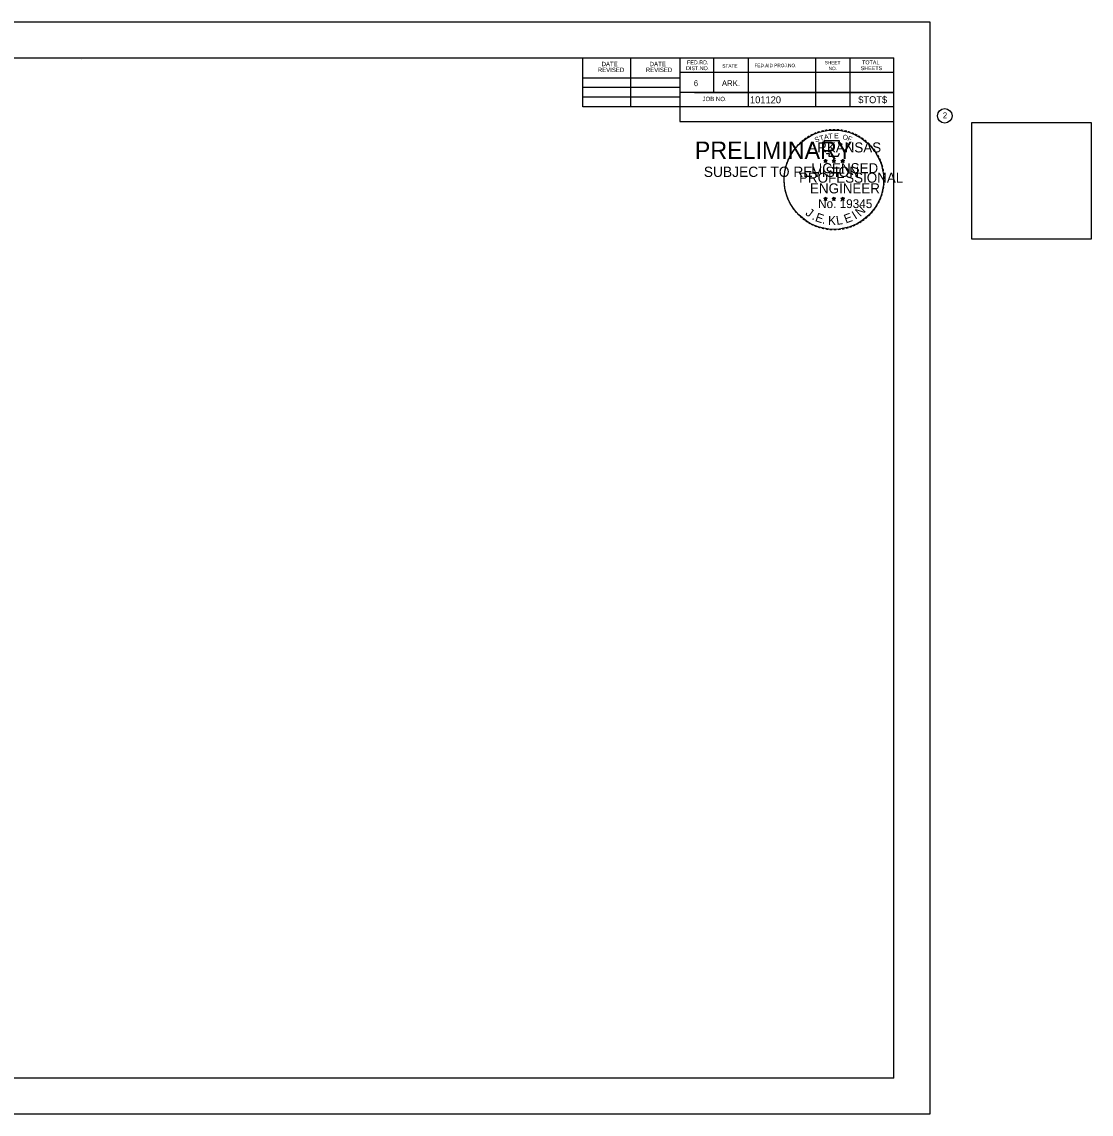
# Model space of a CAD drawing. Extents: x -7.3 to 35.8, y -0.5 to 21.5.
# Drawn here: x 14.21 to 35.75, y -0.5 to 21.5 of the extents above; entities that cross this region are included whole.
import ezdxf

# ---------------------------------------------------------------- set-up
doc = ezdxf.new("R2010")
doc.units = 0
for name, color, linetype in [('B_Border', 7, 'Continuous'), ('R_Border', 7, 'Continuous'), ('R_Border PE', 7, 'Continuous'), ('R_Border Prem', 7, 'Continuous'), ('R_No Plot', 7, 'Continuous')]:
    doc.layers.add(name, color=color, linetype=linetype)

msp = doc.modelspace()

# ---------------------------------------------------------------- linework, layer by layer
at = {"layer": 'B_Border'}
msp.add_lwpolyline([(-1.5, 21.5), (32.5, 21.5), (32.5, -0.5), (-1.5, -0.5)], close=True, dxfattribs=at)
at = {"layer": 'R_Border'}
for p, q in [((0.155, 20.773), (31.773, 20.773)), ((15.407, 20.747), (15.407, 20.747)), ((15.407, 20.747), (15.407, 20.747)), ((25.509, 19.785), (25.509, 20.773)), ((26.477, 19.785), (26.477, 20.773)), ((27.463, 20.773), (27.463, 19.493)), ((28.147, 20.773), (28.147, 20.079)), ((28.841, 20.773), (28.841, 19.785)), ((30.199, 20.773), (30.199, 19.785)), ((30.893, 20.773), (30.893, 19.785)), ((31.773, 0.227), (31.773, 20.773)), ((31.773, 20.479), (27.463, 20.479)), ((31.773, 20.481), (31.773, 20.481)), ((25.509, 20.371), (27.463, 20.371)), ((25.509, 20.185), (27.463, 20.185)), ((31.773, 20.079), (27.463, 20.079)), ((27.759, 20.079), (31.773, 20.079)), ((25.509, 19.991), (27.463, 19.991)), ((31.773, 19.785), (25.509, 19.785)), ((27.463, 19.493), (31.773, 19.493)), ((31.773, 0.227), (0.155, 0.227))]:
    msp.add_line(p, q, dxfattribs=at)
msp.add_circle((32.802, 19.607), 0.147, dxfattribs=at)
at = {"layer": 'R_Border PE'}
for p, q in [((30.365, 18.71), (30.4, 18.699)), ((30.365, 18.71), (30.391, 18.706)), ((30.365, 18.71), (30.389, 18.698)), ((30.4, 18.736), (30.396, 18.71)), ((30.4, 18.699), (30.4, 18.736)), ((30.4, 18.736), (30.405, 18.711)), ((30.434, 18.71), (30.4, 18.699)), ((30.434, 18.71), (30.406, 18.705)), ((30.434, 18.71), (30.415, 18.7)), ((30.534, 18.71), (30.569, 18.699)), ((30.534, 18.71), (30.559, 18.706)), ((30.534, 18.71), (30.557, 18.698)), ((30.569, 18.736), (30.565, 18.71)), ((30.569, 18.699), (30.569, 18.736)), ((30.569, 18.736), (30.573, 18.711)), ((30.603, 18.71), (30.569, 18.699)), ((30.603, 18.71), (30.574, 18.705)), ((30.603, 18.71), (30.583, 18.7)), ((30.711, 18.709), (30.746, 18.698)), ((30.711, 18.709), (30.736, 18.704)), ((30.711, 18.709), (30.735, 18.697)), ((30.746, 18.734), (30.742, 18.709)), ((30.746, 18.698), (30.746, 18.734)), ((30.746, 18.734), (30.75, 18.709)), ((30.782, 18.709), (30.746, 18.698)), ((30.782, 18.709), (30.752, 18.704)), ((30.782, 18.709), (30.76, 18.699)), ((30.378, 18.669), (30.4, 18.699)), ((30.378, 18.669), (30.391, 18.693)), ((30.378, 18.669), (30.399, 18.69)), ((30.422, 18.669), (30.399, 18.69)), ((30.422, 18.669), (30.4, 18.699)), ((30.422, 18.669), (30.407, 18.698)), ((30.546, 18.669), (30.569, 18.699)), ((30.546, 18.669), (30.56, 18.693)), ((30.546, 18.669), (30.568, 18.69)), ((30.59, 18.669), (30.568, 18.69)), ((30.59, 18.669), (30.569, 18.699)), ((30.59, 18.669), (30.575, 18.698)), ((30.724, 18.668), (30.746, 18.698)), ((30.724, 18.668), (30.737, 18.692)), ((30.724, 18.668), (30.746, 18.689)), ((30.767, 18.668), (30.746, 18.698)), ((30.767, 18.668), (30.746, 18.689)), ((30.767, 18.668), (30.754, 18.697)), ((30.364, 17.947), (30.399, 17.935)), ((30.364, 17.947), (30.391, 17.942)), ((30.364, 17.947), (30.389, 17.934)), ((30.378, 17.905), (30.399, 17.935)), ((30.378, 17.905), (30.391, 17.93)), ((30.378, 17.905), (30.399, 17.928)), ((30.399, 17.972), (30.395, 17.947)), ((30.399, 17.935), (30.399, 17.972)), ((30.399, 17.972), (30.404, 17.947)), ((30.434, 17.947), (30.399, 17.935)), ((30.422, 17.905), (30.399, 17.935)), ((30.422, 17.905), (30.399, 17.927)), ((30.434, 17.947), (30.405, 17.942)), ((30.422, 17.905), (30.407, 17.934)), ((30.434, 17.947), (30.415, 17.937)), ((30.533, 17.947), (30.568, 17.935)), ((30.533, 17.947), (30.559, 17.942)), ((30.533, 17.947), (30.557, 17.934)), ((30.546, 17.905), (30.568, 17.935)), ((30.546, 17.905), (30.559, 17.93)), ((30.546, 17.905), (30.568, 17.928)), ((30.568, 17.972), (30.564, 17.947)), ((30.568, 17.935), (30.568, 17.972)), ((30.568, 17.972), (30.572, 17.947)), ((30.603, 17.947), (30.568, 17.935)), ((30.589, 17.905), (30.568, 17.935)), ((30.589, 17.905), (30.568, 17.927)), ((30.603, 17.947), (30.573, 17.942)), ((30.589, 17.905), (30.575, 17.934)), ((30.603, 17.947), (30.581, 17.937)), ((30.711, 17.946), (30.746, 17.934)), ((30.711, 17.946), (30.736, 17.941)), ((30.711, 17.946), (30.735, 17.933)), ((30.724, 17.904), (30.746, 17.934)), ((30.724, 17.904), (30.737, 17.929)), ((30.724, 17.904), (30.746, 17.927)), ((30.746, 17.971), (30.742, 17.946)), ((30.746, 17.934), (30.746, 17.971)), ((30.746, 17.971), (30.75, 17.946)), ((30.782, 17.946), (30.746, 17.934)), ((30.767, 17.904), (30.746, 17.934)), ((30.767, 17.904), (30.746, 17.926)), ((30.782, 17.946), (30.752, 17.941)), ((30.767, 17.904), (30.753, 17.933)), ((30.782, 17.946), (30.76, 17.935))]:
    msp.add_line(p, q, dxfattribs=at)
for points in [[(30.369, 19.101), (30.396, 19.017)], [(30.722, 19.009), (30.737, 19.037), (30.669, 19.035), (30.682, 19.101), (30.369, 19.101)], [(30.4, 18.736), (30.422, 18.669), (30.365, 18.71), (30.434, 18.71), (30.378, 18.669), (30.4, 18.736)], [(30.419, 18.857), (30.419, 18.848), (30.475, 18.846), (30.469, 18.798), (30.658, 18.798), (30.679, 18.852)], [(30.569, 18.736), (30.59, 18.669), (30.534, 18.71), (30.603, 18.71), (30.546, 18.669), (30.569, 18.736)], [(30.746, 18.734), (30.767, 18.668), (30.711, 18.709), (30.782, 18.709), (30.724, 18.668), (30.746, 18.734)], [(30.399, 17.972), (30.422, 17.905), (30.364, 17.947), (30.434, 17.947), (30.378, 17.905), (30.399, 17.972)], [(30.568, 17.972), (30.589, 17.905), (30.533, 17.947), (30.603, 17.947), (30.546, 17.905), (30.568, 17.972)], [(30.746, 17.971), (30.767, 17.904), (30.711, 17.946), (30.782, 17.946), (30.724, 17.904), (30.746, 17.971)]]:
    msp.add_lwpolyline(points, dxfattribs=at)
for centre, radius in [((30.57, 18.321), 1), ((30.399, 18.698), 0.0174), ((30.399, 18.698), 0.0146), ((30.399, 18.698), 0.0117), ((30.399, 18.698), 0.00999), ((30.399, 18.698), 0.00753), ((30.399, 18.698), 0.00499), ((30.399, 18.698), 0.00299), ((30.567, 18.698), 0.0174), ((30.567, 18.698), 0.0146), ((30.567, 18.698), 0.0117), ((30.567, 18.698), 0.00999), ((30.567, 18.698), 0.00753), ((30.567, 18.698), 0.00499), ((30.567, 18.698), 0.00299), ((30.745, 18.697), 0.0174), ((30.745, 18.697), 0.0146), ((30.745, 18.697), 0.0117), ((30.745, 18.697), 0.00999), ((30.745, 18.697), 0.00753), ((30.745, 18.697), 0.00499), ((30.745, 18.697), 0.00299), ((30.399, 17.935), 0.0174), ((30.399, 17.935), 0.0146), ((30.399, 17.935), 0.0117), ((30.399, 17.935), 0.00999), ((30.399, 17.935), 0.00753), ((30.399, 17.935), 0.00499), ((30.399, 17.935), 0.00299), ((30.567, 17.935), 0.0174), ((30.567, 17.935), 0.0146), ((30.567, 17.935), 0.0117), ((30.567, 17.935), 0.00999), ((30.567, 17.935), 0.00753), ((30.567, 17.935), 0.00499), ((30.567, 17.935), 0.00299), ((30.745, 17.934), 0.0174), ((30.745, 17.934), 0.0146), ((30.745, 17.934), 0.0117), ((30.745, 17.934), 0.00999), ((30.745, 17.934), 0.00753), ((30.745, 17.934), 0.00499), ((30.745, 17.934), 0.00299)]:
    msp.add_circle(centre, radius, dxfattribs=at)
at = {"layer": 'R_No Plot'}
msp.add_lwpolyline([(33.345, 19.475), (35.75, 19.475), (35.75, 17.125), (33.345, 17.125)], close=True, dxfattribs=at)

# ---------------------------------------------------------------- texts
at = {"layer": 'R_Border'}
for s, height, p in [('DATE', 0.0879, (25.891, 20.607)), ('DATE', 0.0879, (26.859, 20.607)), ('FED.RD.', 0.0782, (27.611, 20.645)), ('SHEET', 0.0684, (30.385, 20.645)), ('TOTAL', 0.0782, (31.137, 20.645)), ('REVISED', 0.0879, (25.813, 20.489)), ('REVISED', 0.0879, (26.781, 20.489)), ('DIST.NO.', 0.0782, (27.591, 20.527)), ('STATE', 0.0684, (28.323, 20.577)), ('FED.AID PROJ.NO.', 0.0684, (28.969, 20.587)), ('NO.', 0.0684, (30.463, 20.527)), ('SHEETS', 0.0782, (31.109, 20.527)), ('ARK.', 0.1172, (28.313, 20.205)), ('JOB NO.', 0.0879, (27.923, 19.903)), ('2', 0.117, (32.763, 19.558))]:
    msp.add_text(s, height=height, rotation=360, dxfattribs=at).set_placement(p)
for s, height, p in [('6', 0.117, (27.747, 20.205)), ('101120', 0.14, (28.879, 19.86)), ('$TOT$', 0.14, (31.059, 19.862))]:
    msp.add_text(s, height=height, dxfattribs=at).set_placement(p)
at = {"layer": 'R_Border PE'}
for s, height, rotation, p in [('-', 0.161, 36.2317, (29.996, 19.079)), ('-', 0.161, 34.0636, (30.055, 19.119)), ('-', 0.161, 28.7918, (30.115, 19.156)), ('-', 0.161, 24.3072, (30.178, 19.188)), ('S', 0.101, 21.594, (30.203, 19.069)), ('-', 0.161, 19.1761, (30.243, 19.215)), ('T', 0.101, 16.4036, (30.295, 19.102)), ('-', 0.161, 13.6301, (30.319, 19.239)), ('A', 0.101, 11.2132, (30.378, 19.127)), ('-', 0.161, 10.2193, (30.387, 19.255)), ('T', 0.101, 6.0228, (30.463, 19.144)), ('-', 0.161, 5.8968, (30.46, 19.266)), ('-', 0.161, 0.1862, (30.538, 19.273)), ('E', 0.101, 0.8323, (30.575, 19.156)), ('-', 0.161, 357.743, (30.611, 19.272)), ('-', 0.161, 352.1617, (30.685, 19.266)), ('O', 0.101, 350.4515, (30.737, 19.134)), ('-', 0.161, 347.2049, (30.758, 19.255)), ('F', 0.101, 340.0707, (30.833, 19.111)), ('-', 0.161, 342.3362, (30.823, 19.239)), ('-', 0.161, 337.8551, (30.896, 19.217)), ('-', 0.161, 334.1211, (30.96, 19.19)), ('-', 0.161, 329.6409, (31.018, 19.161)), ('-', 0.161, 325.8627, (31.082, 19.125)), ('-', 0.161, 54.2325, (29.778, 18.844)), ('-', 0.161, 50.6142, (29.818, 18.902)), ('-', 0.161, 48.4231, (29.86, 18.95)), ('-', 0.161, 42.9622, (29.905, 18.998)), ('-', 0.161, 38.9507, (29.949, 19.041)), ('-', 0.161, 320.5297, (31.144, 19.082)), ('-', 0.161, 315.5786, (31.205, 19.032)), ('-', 0.161, 309.8797, (31.262, 18.976)), ('-', 0.161, 306.6522, (31.316, 18.916)), ('-', 0.161, 67.7743, (29.687, 18.668)), ('-', 0.161, 62.8713, (29.713, 18.729)), ('-', 0.161, 58.0706, (29.745, 18.791)), ('-', 0.141, 303.6753, (31.363, 18.859)), ('-', 0.161, 299.6684, (31.396, 18.797)), ('-', 0.161, 294.6628, (31.43, 18.736)), ('-', 0.161, 81.2013, (29.633, 18.46)), ('-', 0.161, 75.461, (29.645, 18.532)), ('-', 0.161, 72.3945, (29.666, 18.604)), ('-', 0.161, 290.5728, (31.454, 18.679)), ('-', 0.161, 285.1233, (31.478, 18.62)), ('-', 0.161, 280.5493, (31.499, 18.544)), ('-', 0.161, 94.1959, (29.626, 18.247)), ('-', 0.161, 89.0622, (29.622, 18.32)), ('-', 0.161, 85.1863, (29.624, 18.391)), ('-', 0.161, 276.5962, (31.515, 18.468)), ('-', 0.161, 274.3301, (31.521, 18.395)), ('-', 0.161, 269.9407, (31.524, 18.331)), ('-', 0.161, 98.9479, (29.633, 18.18)), ('-', 0.161, 101.7149, (29.646, 18.106)), ('-', 0.161, 105.4578, (29.663, 18.045)), ('-', 0.161, 255.7626, (31.504, 18.129)), ('-', 0.161, 260.9953, (31.515, 18.198)), ('-', 0.161, 263.5172, (31.522, 18.264)), ('-', 0.161, 109.0874, (29.684, 17.982)), ('-', 0.161, 114.0643, (29.709, 17.922)), ('-', 0.161, 115.7289, (29.741, 17.86)), ('-', 0.161, 120.4471, (29.777, 17.801)), ('-', 0.161, 244.6197, (31.437, 17.926)), ('-', 0.161, 247.8887, (31.464, 17.989)), ('-', 0.161, 252.8681, (31.486, 18.057)), ('-', 0.161, 125.8934, (29.816, 17.745)), ('-', 0.161, 130.7181, (29.864, 17.688)), ('-', 0.161, 134.2238, (29.916, 17.634)), ('J', 0.177, 323.9056, (29.982, 17.623)), ('E', 0.177, 340.8881, (30.179, 17.492)), ('E', 0.177, 20.5042, (30.811, 17.438)), ('I', 0.177, 32.2382, (31, 17.514)), ('N', 0.177, 42.9205, (31.098, 17.567)), ('-', 0.161, 225.7653, (31.265, 17.671)), ('-', 0.161, 231.2538, (31.313, 17.727)), ('-', 0.161, 233.8452, (31.357, 17.785)), ('-', 0.161, 239.0712, (31.397, 17.85)), ('-', 0.161, 138.9338, (29.969, 17.587)), ('-', 0.161, 144.6463, (30.025, 17.546)), ('-', 0.161, 148.0898, (30.081, 17.508)), ('-', 0.161, 151.5704, (30.139, 17.475)), ('-', 0.161, 154.6002, (30.193, 17.451)), ('.', 0.177, 336.3407, (30.114, 17.526)), ('-', 0.161, 158.5612, (30.255, 17.425)), ('.', 0.177, 350.694, (30.325, 17.438)), ('K', 0.177, 359.3149, (30.451, 17.411)), ('L', 0.177, 8.7702, (30.627, 17.408)), ('-', 0.161, 200.7184, (30.923, 17.438)), ('-', 0.161, 204.2516, (30.985, 17.465)), ('-', 0.161, 207.3568, (31.047, 17.498)), ('-', 0.161, 212.2491, (31.104, 17.533)), ('-', 0.161, 215.7363, (31.157, 17.573)), ('-', 0.161, 221.0851, (31.213, 17.619)), ('-', 0.161, 162.7983, (30.324, 17.404)), ('-', 0.161, 167.5555, (30.396, 17.388)), ('-', 0.161, 173.1155, (30.474, 17.377)), ('-', 0.161, 176.5183, (30.549, 17.37)), ('-', 0.161, 181.5918, (30.625, 17.372)), ('-', 0.161, 185.8167, (30.706, 17.381)), ('-', 0.161, 191.2858, (30.781, 17.393)), ('-', 0.161, 195.4743, (30.854, 17.414))]:
    msp.add_text(s, height=height, rotation=rotation, dxfattribs=at).set_placement(p)
for s, height, p in [('ARKANSAS', 0.2016, (30.052, 18.87)), ('LICENSED', 0.2016, (30.112, 18.452)), ('PROFESSIONAL', 0.20156, (29.868, 18.26)), ('ENGINEER', 0.2016, (30.088, 18.045)), ('No. 19345', 0.1771, (30.25, 17.749))]:
    msp.add_text(s, height=height, dxfattribs=at).set_placement(p)
at = {"layer": 'R_Border Prem'}
for s, height, p in [('PRELIMINARY', 0.35, (27.768, 18.739)), ('DWB', 0.002, (27.843, 18.924)), ('SUBJECT TO REVISION', 0.20751, (27.949, 18.376))]:
    msp.add_text(s, height=height, rotation=360, dxfattribs=at).set_placement(p)

doc.saveas('drawing.dxf')
